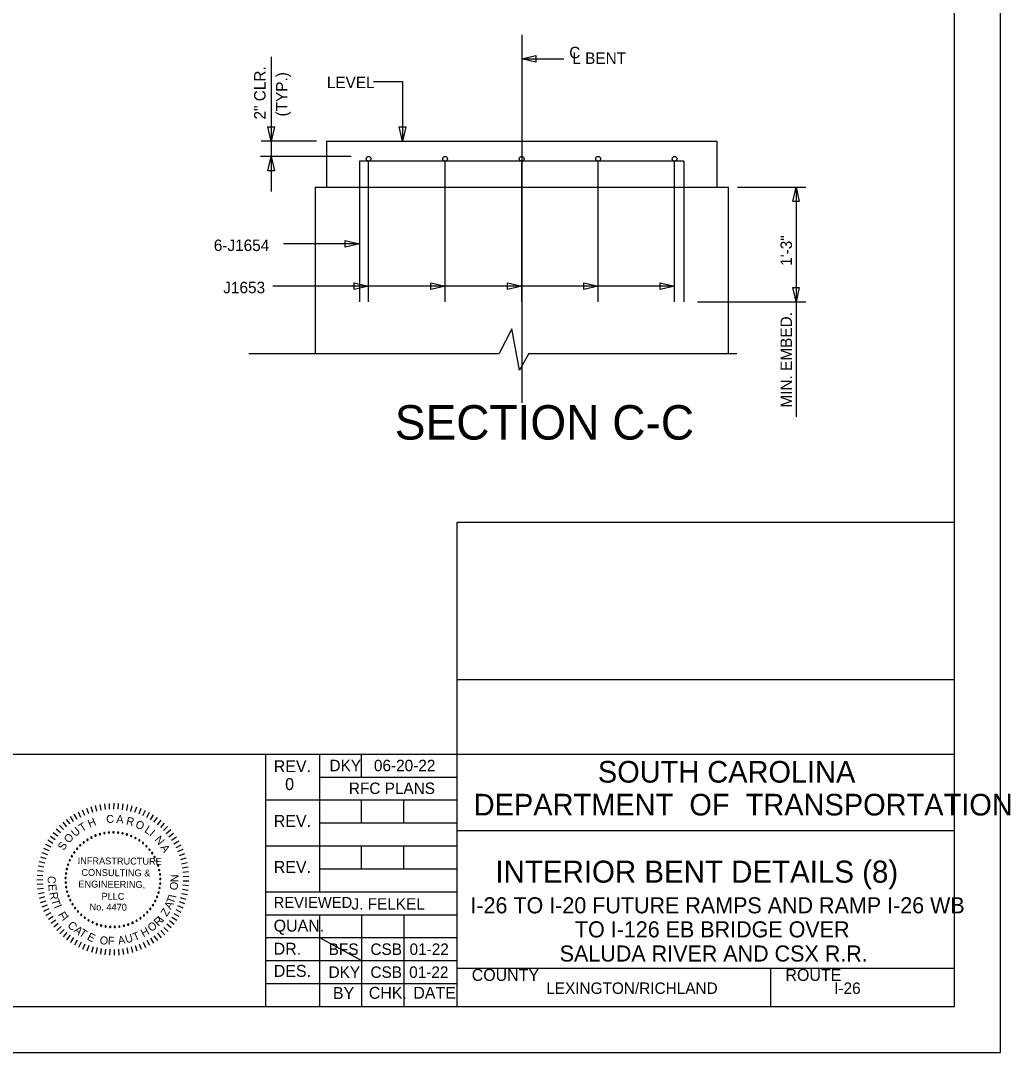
# Model space of a CAD drawing. Extents: x -133.1 to -97, y -58.4 to -36.4.
# Drawn here: x -107.81 to -97.03, y -58.4 to -47.16 of the extents above; entities that cross this region are included whole.
import ezdxf

# ---------------------------------------------------------------- set-up
doc = ezdxf.new("R2010")
doc.units = 0
for name, color, linetype in [('BR_AUTO DIMENSION', 7, 'Continuous'), ('BR_BORDER LINES', 7, 'Continuous'), ('BR_CENTER LINES', 7, 'Continuous'), ('BR_CONCRETE', 7, 'Continuous'), ('BR_REBAR', 7, 'Continuous'), ('BR_TEXT', 7, 'Continuous'), ('Default', 7, 'Continuous'), ('Level 31', 7, 'Continuous')]:
    doc.layers.add(name, color=color, linetype=linetype)

msp = doc.modelspace()

# ---------------------------------------------------------------- linework, layer by layer
at = {"layer": 'BR_AUTO DIMENSION'}
for p, q in [((-105.086, -47.554), (-105.086, -49.019)), ((-102.357, -47.575), (-101.898, -47.575)), ((-103.972, -47.821), (-103.655, -47.821)), ((-103.655, -47.821), (-103.655, -48.471)), ((-104.593, -48.471), (-105.195, -48.471)), ((-104.215, -48.638), (-105.202, -48.638)), ((-100.006, -48.972), (-99.263, -48.972)), ((-99.369, -48.972), (-99.369, -51.476)), ((-104.123, -49.591), (-104.95, -49.591)), ((-100.691, -50.051), (-105.068, -50.051)), ((-104.691, -50.051), (-104.771, -50.051)), ((-103.191, -50.051), (-103.271, -50.051)), ((-102.357, -50.051), (-102.437, -50.051)), ((-101.524, -50.051), (-101.604, -50.051)), ((-100.691, -50.051), (-100.771, -50.051)), ((-100.443, -50.222), (-99.263, -50.222)), ((-100.006, -50.222), (-99.263, -50.222))]:
    msp.add_line(p, q, dxfattribs=at)
for points in [[(-102.201, -47.611), (-102.357, -47.575), (-102.201, -47.539)], [(-105.05, -48.315), (-105.086, -48.471), (-105.122, -48.315)], [(-103.619, -48.315), (-103.655, -48.471), (-103.691, -48.315)], [(-105.122, -48.794), (-105.086, -48.638), (-105.05, -48.794)], [(-99.405, -49.128), (-99.369, -48.972), (-99.333, -49.128)], [(-104.279, -49.555), (-104.123, -49.591), (-104.279, -49.627)], [(-104.18, -50.015), (-104.024, -50.051), (-104.18, -50.087)], [(-103.347, -50.015), (-103.191, -50.051), (-103.347, -50.087)], [(-102.513, -50.015), (-102.357, -50.051), (-102.513, -50.087)], [(-101.68, -50.015), (-101.524, -50.051), (-101.68, -50.087)], [(-100.847, -50.015), (-100.691, -50.051), (-100.847, -50.087)], [(-99.333, -50.066), (-99.369, -50.222), (-99.405, -50.066)]]:
    msp.add_lwpolyline(points, close=True, dxfattribs=at)
at = {"layer": 'BR_BORDER LINES'}
for p, q in [((-97.642, -57.899), (-97.642, -36.899)), ((-103.058, -57.899), (-103.058, -52.622)), ((-103.058, -52.622), (-97.642, -52.622)), ((-103.058, -54.337), (-97.642, -54.337)), ((-110.507, -55.149), (-105.142, -55.149)), ((-105.142, -57.899), (-105.142, -55.149)), ((-105.142, -55.149), (-97.642, -55.149)), ((-104.559, -55.149), (-104.559, -56.649)), ((-104.1, -55.399), (-104.1, -55.149)), ((-104.559, -55.399), (-103.058, -55.399)), ((-105.142, -55.649), (-103.058, -55.649)), ((-104.1, -55.899), (-104.1, -55.649)), ((-103.642, -55.899), (-103.642, -55.649)), ((-104.559, -55.899), (-103.058, -55.899)), ((-103.058, -55.982), (-103.058, -55.982)), ((-103.058, -55.982), (-97.641, -55.982)), ((-105.142, -56.149), (-103.058, -56.149)), ((-104.1, -56.399), (-104.1, -56.149)), ((-103.642, -56.399), (-103.642, -56.149)), ((-104.559, -56.399), (-103.058, -56.399)), ((-105.142, -56.649), (-103.058, -56.649)), ((-105.142, -56.899), (-103.058, -56.899)), ((-104.559, -56.899), (-104.559, -57.899)), ((-104.1, -56.899), (-104.1, -57.899)), ((-103.642, -56.899), (-103.642, -57.899)), ((-105.142, -57.149), (-103.058, -57.149)), ((-105.142, -57.399), (-103.058, -57.399)), ((-103.058, -57.482), (-97.642, -57.482)), ((-102.961, -57.482), (-97.642, -57.482)), ((-99.642, -57.899), (-99.642, -57.482)), ((-105.142, -57.649), (-103.058, -57.649)), ((-131.308, -57.899), (-97.642, -57.899))]:
    msp.add_line(p, q, dxfattribs=at)
at = {"layer": 'BR_CENTER LINES'}
msp.add_line((-102.357, -47.313), (-102.357, -51.322), dxfattribs=at)
at = {"layer": 'BR_CONCRETE'}
for p, q in [((-104.482, -48.471), (-104.482, -48.972)), ((-104.482, -48.471), (-100.232, -48.471)), ((-100.232, -48.471), (-100.232, -48.972)), ((-104.607, -48.972), (-104.607, -50.784)), ((-104.607, -48.972), (-100.107, -48.972)), ((-100.107, -48.972), (-100.107, -50.784))]:
    msp.add_line(p, q, dxfattribs=at)
at = {"layer": 'BR_REBAR'}
for p, q in [((-104.123, -48.69), (-104.123, -50.222)), ((-100.592, -48.69), (-104.123, -48.69)), ((-104.024, -50.222), (-104.024, -48.69)), ((-103.191, -50.222), (-103.191, -48.69)), ((-102.357, -50.222), (-102.357, -48.69)), ((-101.524, -50.222), (-101.524, -48.69)), ((-100.691, -50.222), (-100.691, -48.69)), ((-100.592, -48.69), (-100.592, -50.222))]:
    msp.add_line(p, q, dxfattribs=at)
for centre in [(-104.024, -48.664), (-103.191, -48.664), (-102.357, -48.664), (-101.524, -48.664), (-100.691, -48.664)]:
    msp.add_circle(centre, 0.0261, dxfattribs=at)
at = {"layer": 'BR_TEXT'}
for p, q in [((-107.097, -55.737), (-107.075, -55.797)), ((-107.049, -55.721), (-107.031, -55.782)), ((-107.001, -55.708), (-106.986, -55.77)), ((-106.951, -55.698), (-106.94, -55.76)), ((-106.901, -55.69), (-106.894, -55.754)), ((-106.851, -55.686), (-106.848, -55.75)), ((-106.8, -55.685), (-106.801, -55.749)), ((-106.75, -55.687), (-106.754, -55.751)), ((-106.7, -55.692), (-106.708, -55.755)), ((-106.65, -55.7), (-106.662, -55.763)), ((-106.601, -55.712), (-106.617, -55.773)), ((-106.552, -55.726), (-106.572, -55.786)), ((-106.505, -55.743), (-106.528, -55.802)), ((-107.317, -55.86), (-107.278, -55.91)), ((-107.276, -55.83), (-107.24, -55.883)), ((-107.234, -55.803), (-107.201, -55.857)), ((-107.189, -55.778), (-107.16, -55.835)), ((-107.144, -55.756), (-107.118, -55.814)), ((-106.458, -55.763), (-106.485, -55.821)), ((-106.413, -55.786), (-106.444, -55.842)), ((-106.37, -55.811), (-106.403, -55.865)), ((-106.328, -55.839), (-106.365, -55.891)), ((-107.427, -55.963), (-107.38, -56.005)), ((-107.392, -55.927), (-107.348, -55.972)), ((-107.356, -55.892), (-107.314, -55.94)), ((-106.288, -55.87), (-106.328, -55.919)), ((-106.249, -55.903), (-106.292, -55.95)), ((-106.213, -55.938), (-106.259, -55.982)), ((-107.517, -56.085), (-107.462, -56.118)), ((-107.489, -56.043), (-107.437, -56.079)), ((-107.46, -56.002), (-107.409, -56.041)), ((-106.179, -55.975), (-106.227, -56.017)), ((-106.148, -56.014), (-106.198, -56.053)), ((-106.118, -56.056), (-106.171, -56.091)), ((-107.564, -56.174), (-107.506, -56.2)), ((-107.542, -56.129), (-107.485, -56.159)), ((-106.092, -56.099), (-106.147, -56.131)), ((-106.068, -56.143), (-106.125, -56.172)), ((-106.047, -56.189), (-106.105, -56.214)), ((-107.599, -56.269), (-107.538, -56.288)), ((-107.583, -56.221), (-107.523, -56.244)), ((-106.028, -56.236), (-106.088, -56.257)), ((-106.013, -56.284), (-106.074, -56.302)), ((-107.63, -56.417), (-107.567, -56.424)), ((-107.623, -56.367), (-107.56, -56.378)), ((-107.613, -56.318), (-107.551, -56.333)), ((-106, -56.333), (-106.063, -56.347)), ((-105.991, -56.382), (-106.054, -56.393)), ((-107.636, -56.518), (-107.572, -56.517)), ((-107.635, -56.467), (-107.571, -56.471)), ((-105.985, -56.433), (-106.048, -56.439)), ((-105.981, -56.483), (-106.045, -56.485)), ((-105.981, -56.533), (-106.045, -56.532)), ((-107.634, -56.568), (-107.571, -56.564)), ((-107.629, -56.618), (-107.566, -56.61)), ((-105.989, -56.634), (-106.052, -56.625)), ((-105.984, -56.584), (-106.047, -56.578)), ((-107.621, -56.668), (-107.559, -56.656)), ((-107.61, -56.718), (-107.549, -56.702)), ((-107.596, -56.766), (-107.536, -56.746)), ((-106.025, -56.781), (-106.085, -56.76)), ((-106.01, -56.733), (-106.072, -56.716)), ((-105.998, -56.684), (-106.061, -56.671)), ((-107.579, -56.814), (-107.52, -56.79)), ((-107.56, -56.86), (-107.502, -56.833)), ((-106.064, -56.874), (-106.121, -56.847)), ((-106.043, -56.828), (-106.102, -56.804)), ((-107.537, -56.905), (-107.481, -56.875)), ((-107.512, -56.949), (-107.458, -56.915)), ((-107.484, -56.991), (-107.432, -56.954)), ((-106.142, -57.004), (-106.193, -56.966)), ((-106.113, -56.962), (-106.167, -56.928)), ((-106.087, -56.919), (-106.143, -56.888)), ((-107.454, -57.031), (-107.404, -56.991)), ((-107.421, -57.07), (-107.374, -57.027)), ((-107.386, -57.106), (-107.341, -57.06)), ((-107.348, -57.14), (-107.307, -57.092)), ((-106.242, -57.117), (-106.286, -57.07)), ((-106.207, -57.081), (-106.253, -57.038)), ((-106.173, -57.043), (-106.222, -57.003)), ((-107.309, -57.172), (-107.271, -57.121)), ((-107.268, -57.201), (-107.233, -57.148)), ((-107.225, -57.228), (-107.193, -57.173)), ((-107.181, -57.252), (-107.152, -57.195)), ((-106.45, -57.259), (-106.477, -57.202)), ((-106.405, -57.236), (-106.436, -57.18)), ((-106.362, -57.21), (-106.396, -57.156)), ((-106.32, -57.181), (-106.358, -57.13)), ((-106.28, -57.15), (-106.321, -57.101)), ((-107.135, -57.273), (-107.11, -57.215)), ((-107.088, -57.292), (-107.067, -57.232)), ((-107.04, -57.307), (-107.022, -57.246)), ((-106.991, -57.32), (-106.977, -57.258)), ((-106.942, -57.33), (-106.932, -57.267)), ((-106.892, -57.336), (-106.885, -57.273)), ((-106.841, -57.34), (-106.839, -57.276)), ((-106.791, -57.34), (-106.792, -57.277)), ((-106.74, -57.338), (-106.746, -57.274)), ((-106.69, -57.332), (-106.699, -57.269)), ((-106.641, -57.323), (-106.654, -57.261)), ((-106.592, -57.312), (-106.608, -57.25)), ((-106.543, -57.297), (-106.564, -57.237)), ((-106.496, -57.279), (-106.52, -57.22))]:
    msp.add_line(p, q, dxfattribs=at)
for centre, start, end in [((-107.086, -56.083), 32.7576, 212.7576), ((-107.086, -56.083), 212.7576, 32.7576), ((-107.043, -56.058), 27.2191, 207.2191), ((-107.043, -56.058), 207.2191, 27.2191), ((-106.998, -56.037), 21.6807, 201.6807), ((-106.998, -56.037), 201.6807, 21.6807), ((-106.951, -56.021), 16.1422, 196.1422), ((-106.951, -56.021), 196.1422, 16.1422), ((-106.902, -56.01), 10.6038, 190.6038), ((-106.902, -56.01), 190.6038, 10.6038), ((-106.853, -56.003), 5.0653, 185.0653), ((-106.853, -56.003), 185.0653, 5.0653), ((-106.803, -56.001), 359.5268, 179.5268), ((-106.803, -56.001), 179.5268, 359.5268), ((-106.753, -56.004), 353.9884, 173.9884), ((-106.753, -56.004), 173.9884, 353.9884), ((-106.704, -56.012), 348.4499, 168.4499), ((-106.704, -56.012), 168.4499, 348.4499), ((-106.656, -56.024), 162.9114, 342.9114), ((-106.656, -56.024), 342.9114, 162.9114), ((-106.609, -56.041), 157.373, 337.373), ((-106.609, -56.041), 337.373, 157.373), ((-106.564, -56.063), 151.8345, 331.8345), ((-106.564, -56.063), 331.8345, 151.8345), ((-106.521, -56.089), 146.2961, 326.2961), ((-106.521, -56.089), 326.2961, 146.2961), ((-107.199, -56.181), 49.373, 229.373), ((-107.199, -56.181), 229.373, 49.373), ((-107.165, -56.144), 43.8345, 223.8345), ((-107.165, -56.144), 223.8345, 43.8345), ((-107.127, -56.112), 38.2961, 218.2961), ((-107.127, -56.112), 218.2961, 38.2961), ((-106.481, -56.118), 140.7576, 320.7576), ((-106.481, -56.118), 320.7576, 140.7576), ((-106.444, -56.152), 135.2191, 315.2191), ((-106.444, -56.152), 315.2191, 135.2191), ((-106.411, -56.189), 129.6807, 309.6807), ((-106.411, -56.189), 309.6807, 129.6807), ((-107.279, -56.306), 65.9884, 245.9884), ((-107.279, -56.306), 245.9884, 65.9884), ((-107.256, -56.262), 60.4499, 240.4499), ((-107.256, -56.262), 240.4499, 60.4499), ((-107.23, -56.22), 54.9114, 234.9114), ((-107.23, -56.22), 234.9114, 54.9114), ((-106.381, -56.228), 124.1422, 304.1422), ((-106.381, -56.228), 304.1422, 124.1422), ((-106.355, -56.271), 118.6038, 298.6038), ((-106.355, -56.271), 298.6038, 118.6038), ((-106.333, -56.316), 113.0653, 293.0653), ((-106.333, -56.316), 293.0653, 113.0653), ((-107.311, -56.401), 77.0653, 257.0653), ((-107.311, -56.401), 257.0653, 77.0653), ((-107.297, -56.353), 71.5268, 251.5268), ((-107.297, -56.353), 251.5268, 71.5268), ((-106.316, -56.363), 107.5268, 287.5268), ((-106.316, -56.363), 287.5268, 107.5268), ((-106.304, -56.411), 101.9884, 281.9884), ((-106.304, -56.411), 281.9884, 101.9884), ((-107.324, -56.499), 88.1422, 268.1422), ((-107.319, -56.45), 82.6038, 262.6038), ((-107.324, -56.499), 268.1422, 88.1422), ((-107.319, -56.45), 262.6038, 82.6038), ((-106.296, -56.46), 96.4499, 276.4499), ((-106.293, -56.51), 90.9114, 270.9114), ((-106.296, -56.46), 276.4499, 96.4499), ((-106.293, -56.51), 270.9114, 90.9114), ((-107.323, -56.549), 93.6807, 273.6807), ((-107.317, -56.599), 99.2191, 279.2191), ((-107.323, -56.549), 273.6807, 93.6807), ((-107.317, -56.599), 279.2191, 99.2191), ((-107.307, -56.647), 104.7576, 284.7576), ((-107.307, -56.647), 284.7576, 104.7576), ((-106.301, -56.609), 79.8345, 259.8345), ((-106.301, -56.609), 259.8345, 79.8345), ((-106.294, -56.56), 85.373, 265.373), ((-106.294, -56.56), 265.373, 85.373), ((-107.292, -56.695), 110.2961, 290.2961), ((-107.292, -56.695), 290.2961, 110.2961), ((-107.273, -56.741), 115.8345, 295.8345), ((-107.273, -56.741), 295.8345, 115.8345), ((-106.348, -56.75), 63.2191, 243.2191), ((-106.348, -56.75), 243.2191, 63.2191), ((-106.328, -56.705), 68.7576, 248.7576), ((-106.328, -56.705), 248.7576, 68.7576), ((-106.312, -56.658), 74.2961, 254.2961), ((-106.312, -56.658), 254.2961, 74.2961), ((-107.249, -56.785), 121.373, 301.373), ((-107.249, -56.785), 301.373, 121.373), ((-107.221, -56.826), 126.9114, 306.9114), ((-107.221, -56.826), 306.9114, 126.9114), ((-107.189, -56.864), 132.4499, 312.4499), ((-107.189, -56.864), 312.4499, 132.4499), ((-106.434, -56.872), 46.6038, 226.6038), ((-106.434, -56.872), 226.6038, 46.6038), ((-106.402, -56.834), 52.1422, 232.1422), ((-106.402, -56.834), 232.1422, 52.1422), ((-106.373, -56.794), 57.6807, 237.6807), ((-106.373, -56.794), 237.6807, 57.6807), ((-107.154, -56.9), 137.9884, 317.9884), ((-107.154, -56.9), 317.9884, 137.9884), ((-107.116, -56.931), 143.5268, 323.5268), ((-107.116, -56.931), 323.5268, 143.5268), ((-107.074, -56.959), 149.0653, 329.0653), ((-107.074, -56.959), 329.0653, 149.0653), ((-107.03, -56.982), 334.6038, 154.6038), ((-107.03, -56.982), 154.6038, 334.6038), ((-106.596, -56.987), 24.4499, 204.4499), ((-106.596, -56.987), 204.4499, 24.4499), ((-106.551, -56.964), 29.9884, 209.9884), ((-106.551, -56.964), 209.9884, 29.9884), ((-106.509, -56.937), 35.5268, 215.5268), ((-106.509, -56.937), 215.5268, 35.5268), ((-106.47, -56.907), 41.0653, 221.0653), ((-106.47, -56.907), 221.0653, 41.0653), ((-106.984, -57.002), 340.1422, 160.1422), ((-106.984, -57.002), 160.1422, 340.1422), ((-106.937, -57.016), 345.6807, 165.6807), ((-106.937, -57.016), 165.6807, 345.6807), ((-106.888, -57.027), 351.2191, 171.2191), ((-106.888, -57.027), 171.2191, 351.2191), ((-106.838, -57.032), 356.7576, 176.7576), ((-106.838, -57.032), 176.7576, 356.7576), ((-106.789, -57.032), 2.2961, 182.2961), ((-106.789, -57.032), 182.2961, 2.2961), ((-106.739, -57.028), 7.8345, 187.8345), ((-106.739, -57.028), 187.8345, 7.8345), ((-106.69, -57.019), 13.373, 193.373), ((-106.69, -57.019), 193.373, 13.373), ((-106.642, -57.005), 18.9114, 198.9114), ((-106.642, -57.005), 198.9114, 18.9114)]:
    msp.add_arc(centre, 0.00701, start, end, dxfattribs=at)
at = {"layer": 'Default'}
for p, q in [((-105.327, -50.784), (-102.603, -50.784)), ((-102.28, -50.784), (-100.013, -50.784))]:
    msp.add_line(p, q, dxfattribs=at)
msp.add_lwpolyline([(-102.28, -50.784), (-102.379, -50.967), (-102.464, -50.515), (-102.603, -50.784)], dxfattribs=at)
at = {"layer": 'Level 31'}
for p, q in [((-100.35, -56.422), (-100.35, -56.422)), ((-104.559, -57.149), (-104.1, -57.399))]:
    msp.add_line(p, q, dxfattribs=at)
msp.add_lwpolyline([(-133.141, -58.399), (-97.141, -58.399), (-97.141, -36.399), (-133.141, -36.399)], close=True, dxfattribs=at)

# ---------------------------------------------------------------- texts
at = {"layer": 'BR_AUTO DIMENSION'}
for s, rotation, p in [('C', 360, (-101.839, -47.569)), ('L BENT', 360, (-101.805, -47.63)), ('2" CLR.', 90, (-105.146, -48.236)), ('(TYP.)', 90, (-104.908, -48.203)), ('LEVEL', 360, (-104.479, -47.894)), ('6-J1654', 360, (-105.71, -49.669)), ('1\'-3" ', 90, (-99.413, -49.83)), ('J1653', 360, (-105.607, -50.129)), ('MIN. EMBED.', 90, (-99.413, -51.374))]:
    msp.add_text(s, height=0.125, rotation=rotation, dxfattribs=at).set_placement(p)
at = {"layer": 'BR_TEXT'}
for s, height, rotation, p in [('SECTION C-C', 0.375, 360, (-103.739, -51.723)), ('H', 0.0872, 22.7882, (-107.061, -55.952)), ('C', 0.0872, 4.7281, (-106.878, -55.903)), ('A', 0.0872, 355.6981, (-106.774, -55.898)), ('R', 0.0872, 346.6681, (-106.67, -55.915)), ('U', 0.0872, 40.8482, (-107.219, -56.056)), ('T', 0.0872, 31.8182, (-107.146, -56)), ('O', 0.0872, 337.638, (-106.572, -55.945)), ('L', 0.0872, 327.108, (-106.473, -55.995)), ('I', 0.0872, 319.578, (-106.421, -56.033)), ('O', 0.0872, 49.8782, (-107.286, -56.127)), ('N', 0.0872, 310.548, (-106.36, -56.084)), ('S', 0.0872, 58.9083, (-107.342, -56.205)), ('A', 0.0872, 301.5179, (-106.295, -56.166)), ('INFRASTRUCTURE', 0.07477, 359.5268, (-107.193, -56.348)), ('CONSULTING &', 0.07477, 359.5268, (-107.152, -56.476)), ('C', 0.0872, 267.025, (-107.517, -56.475)), ('ENGINEERING,', 0.07477, 359.5268, (-107.185, -56.602)), ('N', 0.0872, 89.2085, (-106.095, -56.545)), ('E', 0.0872, 273.025, (-107.512, -56.567)), ('O', 0.0872, 83.2085, (-106.106, -56.636)), ('R', 0.0872, 279.025, (-107.5, -56.659)), ('T', 0.0872, 285.025, (-107.482, -56.738)), ('PLLC', 0.0748, 359.5268, (-106.934, -56.735)), ('T', 0.0872, 69.3954, (-106.148, -56.788)), ('I', 0.0872, 77.9093, (-106.122, -56.721)), ('I', 0.0872, 293.7713, (-107.453, -56.811)), ('F', 0.0872, 299.7713, (-107.411, -56.897)), ('No. 4470', 0.0748, 359.5268, (-107.063, -56.852)), ('Z', 0.0872, 57.3954, (-106.222, -56.925)), ('A', 0.0872, 63.3954, (-106.178, -56.848)), ('I', 0.0872, 308.5268, (-107.369, -56.951)), ('C', 0.0872, 314.5268, (-107.31, -57.021)), ('O', 0.0872, 38.5268, (-106.389, -57.09)), ('R', 0.0872, 44.5268, (-106.313, -57.03)), ('I', 0.0872, 52.3339, (-106.263, -56.982)), ('A', 0.0872, 320.5268, (-107.241, -57.079)), ('T', 0.0872, 326.5268, (-107.186, -57.118)), ('E', 0.0872, 332.5268, (-107.098, -57.166)), ('T', 0.0872, 22.5268, (-106.571, -57.188)), ('H', 0.0872, 28.5268, (-106.477, -57.146)), ('O', 0.0872, 350.5268, (-106.958, -57.215)), ('F', 0.0872, 356.5268, (-106.866, -57.224)), ('A', 0.0872, 10.5268, (-106.746, -57.225)), ('U', 0.0872, 16.5268, (-106.662, -57.212))]:
    msp.add_text(s, height=height, rotation=rotation, dxfattribs=at).set_placement(p)
for s, height, p in [('REV.', 0.13, (-105.057, -55.346)), ('DKY', 0.125, (-104.45, -55.336)), ('06-20-22', 0.125, (-103.966, -55.336)), ('SOUTH CAROLINA', 0.23587, (-101.527, -55.46)), ('0', 0.13, (-104.933, -55.541)), ('RFC PLANS', 0.125, (-104.239, -55.584)), ('DEPARTMENT  OF  TRANSPORTATION', 0.23587, (-102.879, -55.818)), ('REV.', 0.13, (-105.057, -55.943)), ('INTERIOR BENT DETAILS (8)', 0.24, (-102.643, -56.55)), ('REV.', 0.13, (-105.057, -56.443)), ('REVIEWED', 0.12, (-105.058, -56.825)), ('J. FELKEL', 0.125, (-104.211, -56.844)), ('I-26 TO I-20 FUTURE RAMPS AND RAMP I-26 WB', 0.175, (-102.915, -56.884)), ('QUAN.', 0.13, (-105.058, -57.083)), ('TO I-126 EB BRIDGE OVER', 0.175, (-101.777, -57.146)), ('DR.', 0.13, (-105.058, -57.335)), ('BFS', 0.125, (-104.459, -57.337)), ('CSB', 0.125, (-104.004, -57.337)), ('01-22', 0.125, (-103.578, -57.337)), ('SALUDA RIVER AND CSX R.R.', 0.175, (-101.943, -57.409)), ('DES.', 0.13, (-105.057, -57.576)), ('DKY', 0.125, (-104.46, -57.587)), ('CSB', 0.125, (-104.004, -57.587)), ('01-22', 0.125, (-103.582, -57.587)), ('COUNTY', 0.13, (-102.901, -57.62)), ('ROUTE', 0.13, (-99.484, -57.62)), ('LEXINGTON/RICHLAND', 0.12499, (-102.089, -57.762)), ('I-26', 0.125, (-98.953, -57.762)), ('BY', 0.13, (-104.413, -57.817)), ('CHK.', 0.13, (-104.022, -57.815)), ('DATE', 0.13, (-103.537, -57.815))]:
    msp.add_text(s, height=height, dxfattribs=at).set_placement(p)

doc.saveas('drawing.dxf')
